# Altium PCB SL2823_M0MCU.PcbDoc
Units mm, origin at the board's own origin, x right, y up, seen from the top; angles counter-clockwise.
Board outline 146.3 x 32.54 mm, 2 copper layers (TopLayer, BottomLayer); 114 components, 64 nets, 342 pads, 170 vias.
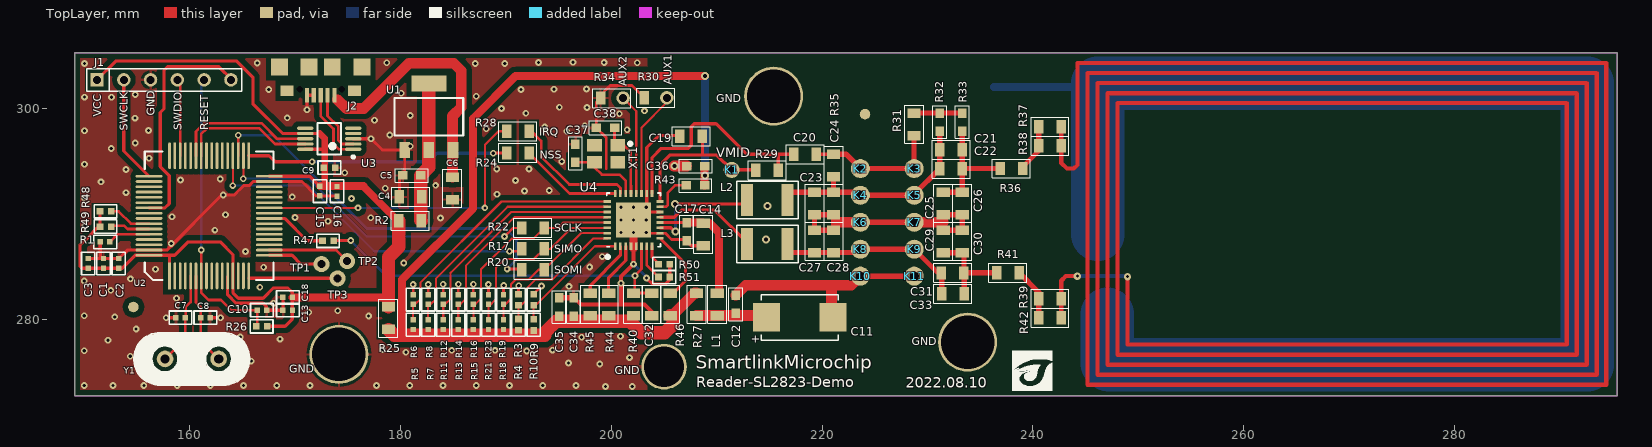
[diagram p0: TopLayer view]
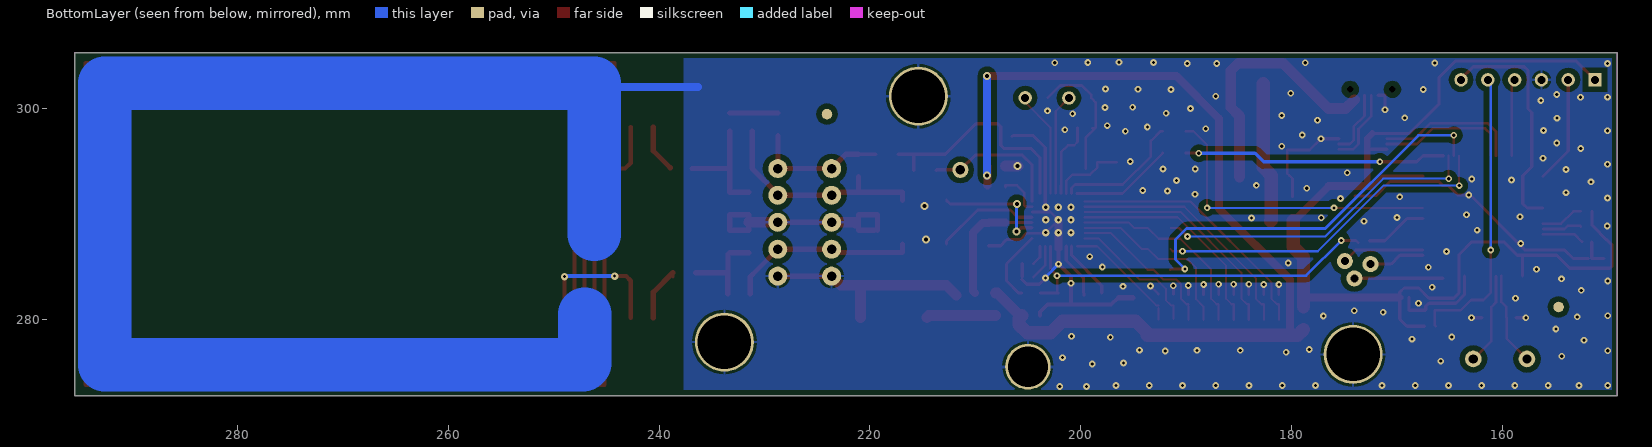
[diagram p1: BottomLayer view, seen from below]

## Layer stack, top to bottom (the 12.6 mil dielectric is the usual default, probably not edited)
TopSolder: solder mask 0.0102, Solder Resist, Dk 3.5
TopLayer: signal copper 0.0356
Dielectric1: dielectric 0.32, FR-4, Dk 4.8
BottomLayer: signal copper 0.0356
BottomSolder: solder mask 0.0102, Solder Resist, Dk 3.5

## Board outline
149.123,272.745 149.123,305.283 295.427,305.283 295.427,272.745

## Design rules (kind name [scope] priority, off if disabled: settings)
Clearance [All] p1: gap=0.152
FabricationTestPointUsage TestPointUsage [All] p1: valid=0 allowmultiple=FALSE
FabricationTestpoint Testpoint [All] p1: side=3 testpointundercomponent=TRUE minsize=1.016 maxsize=2.54 preferedsize=1.524 minholesize=0.508 maxholesize=1.016 preferedholesize=0.813 testpointgrid=0.025 allowsidetop=TRUE allowsidebottom=TRUE usegrid=TRUE gridtolerance=0
HoleSize [All] p1: absolutevalues=TRUE maxlimit=5.08 minlimit=0.025 maxpercent=80.000 minpercent=20.000
PolygonConnect [IsVia] p1: connectstyle=Direct reliefconductorwidth=0.254 reliefentries=4 polygonreliefangle="90 Angle" airgapwidth=0.254
PolygonConnect PolygonConnect_1 [All] p2: connectstyle=Relief reliefconductorwidth=0.254 reliefentries=4 polygonreliefangle="90 Angle" airgapwidth=0.254
RoutingVias [All] p1: holewidth=0.381 width=0.762 viastyle="Through Hole" minholewidth=0.254 minwidth=0.508 maxholewidth=0.508 maxwidth=1.27
SolderMaskExpansion [All] p1: expansion=0.102
Width [All] p1: maxlimit=7.62 minlimit=0.076 preferedwidth=0.203
27 further rules are at their usual default settings.

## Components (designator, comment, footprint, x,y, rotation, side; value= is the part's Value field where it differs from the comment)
C1 "100p" C_0402#1 151.867,284.836 r90 top
C2 "Cap" C_0402#1 153.314,284.836 r90 top
C3 "0.1u" C_0402#1 150.419,284.836 r90 top
C4 "10uF" Y0805#1 181,291.592 r180 top
C5 "0.1uF" Y0603 181.102,293.624 r180 top
C6 "10uF" Y0805#1 184.963,292.405 r270 top
C7 "12pF" C_0402#1 158.725,280.137 r0 top
C8 "12pF" C_0402#1 161.087,280.137 r0 top
C9 "Cap" C_0402#2 172.847,294.361 r0 top
C10 "2.2uF" C_0402#1 166.446,280.848 r0 top
C11 "330uF" C_TANTAL_D 217.881,280.162 r0 top
C12 "100nF" Y0603 211.815,281.403 r270 top
C13 "0.1uF" C_0402#1 169.799,280.848 r180 top
C14 "100pF" Y0805#1 208.737,288.036 r90 top
C15 "Cap" C_0402#1 172.39,291.694 r90 top
C16 "Cap" C_0402#1 174.015,292.583 r270 top
C17 "100nF" Y0603 207.162,288.29 r90 top
C18 "100p" C_0402#1 169.799,282.067 r180 top
C19 "1nF" Y0805#1 207.594,297.332 r180 top
C20 "1nF" Y0805#1 218.392,295.628 r0 top
C21 "12pF" Y0805#1 232.242,296.078 r0 top
C22 "27pF" Y0805#1 232.242,294.278 r0 top
C23 "270pF" Y0805#1 219.292,290.978 r90 top
C24 "NC" Y0805#1 221.092,290.978 r90 top
C25 "100pF" Y0805#1 231.492,290.978 r90 top
C26 "6pF" Y0805#1 233.292,290.978 r90 top
C27 "270pF" Y0805#1 219.292,287.378 r90 top
C28 "NC" Y0805#1 221.092,287.378 r90 top
C29 "100pF" Y0805#1 231.492,287.378 r90 top
C30 "6pF" Y0805#1 233.292,287.378 r90 top
C31 "27pF" Y0805#1 232.392,284.378 r0 top
C32 "Cap" Y0805#1 203.871,281.407 r90 top
C33 "12pF" Y0805#1 232.412,282.408 r0 top
C34 "100nF" Y0603 196.444,281.153 r270 top
C35 "100nF" Y0603 195.072,281.153 r270 top
C36 "100pF" Y0603 208.026,294.513 r0 top
C37 "12pF" Y0603 196.621,295.732 r270 top
C38 "12pF" Y0603 199.466,298.145 r0 top
J1 "Header 3X2" JETAG-2 151.257,302.692 r90 top
J2 "USB-B" microusb 172.466,300.558 r180 top
K1 "TP1" TEST_Point#1 211.43,294.157 r0 top
K2 "TP_0.9mm" TP_0.9mm#1 223.749,294.183 r0 top
K3 "TP_0.9mm" TP_0.9mm#2 228.742,294.278 r0 top
K4 "TP_0.9mm" TP_0.9mm#2 223.641,291.741 r0 top
K5 "TP_0.9mm" TP_0.9mm#2 228.741,291.741 r0 top
K6 "TP_0.9mm" TP_0.9mm#2 223.641,289.18 r0 top
K7 "TP_0.9mm" TP_0.9mm#2 228.741,289.18 r0 top
K8 "TP_0.9mm" TP_0.9mm#2 223.641,286.63 r0 top
K9 "TP_0.9mm" TP_0.9mm#2 228.741,286.63 r0 top
K10 "TP_0.9mm" TP_0.9mm#2 223.641,284.08 r0 top
K11 "TP_0.9mm" TP_0.9mm#2 228.741,284.08 r0 top
L1 "22nH" Y0805#1 210.058,281.407 r270 top
L2 "470nH / shielded (1210)" INDCC_1812 214.833,291.287 r0 top locked
L3 "470nH / shielded (1210)" INDCC_1812 214.833,287.122 r0 top locked
R1 "10K" R_0402#1 152.476,287.325 r180 top
R2 "16.9" Y0805#1 180.95,289.331 r0 top
R3 "16.9" R_0402#2 191.23,282.296 r270 top
R4 "16.9" R_0402#2 191.23,279.019 r90 top
R5 "0" R_0402#1 181.229,279.019 r90 top
R6 "0" R_0402#1 181.229,281.407 r90 top
R7 "0" R_0402#1 182.658,279.019 r90 top
R8 "0" R_0402#1 182.658,281.407 r90 top
R9 "16.9" R_0402#2 192.659,282.296 r270 top
R10 "16.9" R_0402#2 192.659,279.908 r270 top
R11 "0" R_0402#1 184.087,279.019 r90 top
R12 "0" R_0402#1 184.087,281.407 r90 top
R13 "0" R_0402#1 185.515,279.019 r90 top
R14 "0" R_0402#1 185.515,281.407 r90 top
R15 "0" R_0402#1 186.944,279.019 r90 top
R16 "0" R_0402#1 186.944,281.407 r90 top
R17 "0R" Y0805#1 192.583,286.664 r180 top
R18 "0" R_0402#1 189.802,279.019 r90 top
R19 "0" R_0402#1 189.802,281.407 r90 top
R20 "0R DNP" Y0805#1 192.608,284.683 r180 top
R21 "0" R_0402#1 188.373,279.019 r90 top
R22 "0R" Y0805#1 192.583,288.646 r0 top
R23 "" R_0402#1 188.373,281.407 r90 top
R24 "0R" Y0805#1 191.16,295.758 r0 top
R25 "16.9" Y0805#1 178.892,280.086 r90 top
R26 "4.7K" R_0402#2 166.421,279.324 r0 top
R27 "0R" Y0805#1 208.102,281.407 r90 top
R28 "0R" Y0805#1 191.16,297.815 r180 top
R29 "160R" Y0805#1 214.792,294.128 r180 top
R30 "NC" Y0805#2 204.216,300.99 r0 top
R31 "2k4" Y0805#1 228.727,298.475 r270 top
R32 "16.9" Y0603 231.165,298.679 r90 top
R33 "16.9" Y0603 233.299,298.679 r90 top
R34 "NC" Y0805#2 200.076,300.965 r0 top
R35 "DNP" Y0805#1 221.092,294.578 r270 top
R36 "0R" Y0805#3 239.014,294.284 r180 top
R37 "3R" Y0805#1 241.619,298.228 r180 top
R38 "3R" Y0805#1 241.619,296.428 r180 top
R39 "3R" Y0805#1 241.619,281.928 r180 top
R40 "10k" Y0805#1 202.123,281.407 r90 top
R41 "0R DNP" Y0805#3 238.684,284.404 r180 top
R42 "3R" Y0805#1 241.619,280.128 r180 top
R43 "16.9" Y0603 208.012,292.683 r180 top
R44 "16.9" Y0805#1 199.766,281.407 r90 top
R45 "16.9" Y0805#1 198.018,281.407 r90 top
R46 "0R DNP" Y0805#1 205.618,281.407 r90 top
R47 "NC" R_0402#2 172.72,287.426 r0 top
R48 "NC" R_0402#2 151.613,290.22 r0 top
R49 "NC" R_0402#2 151.613,288.773 r0 top
R50 "NC" R_0402#2 205.486,285.217 r180 top
R51 "0R" R_0402#2 205.486,283.997 r180 top
TP1 "Test_Point" TEST_Point#2 172.542,285.217 r90 top
TP2 "Test_Point" TEST_Point#2 174.981,285.496 r90 top
TP3 "Test_Point" TEST_Point#2 174.066,283.87 r90 top
U1 "RT9183-33GGF" RT9183-33GG 180.442,296.037 r0 top
U2 "STM32F051R8T6" QFN64-STM32 158.139,284.099 r0 top locked
U3 "CH340E" CH340E_MSOP10 173.279,297.104 r180 top
U4 "SL2x23" Z_QFN50P500X500X100-32N 200.387,286.908 r0 top locked
XT1 "27.12MHz" QUARTZ_32SMX 199.54,295.682 r180 top
Y1 "16MHz" Z-OSC 162.789,276.224 r180 top

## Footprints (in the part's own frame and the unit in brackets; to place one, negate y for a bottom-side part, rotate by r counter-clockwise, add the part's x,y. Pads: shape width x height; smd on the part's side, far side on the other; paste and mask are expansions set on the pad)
C_0402#1 [mil]
  rect 20x20 smd: 1(0,0) 2(36,0)
  silkscreen extent -25,-25 60,25
C_0402#2 [mil]
  rect 25x25 smd: 1(-3,0) 2(39,0)
  silkscreen extent -25,-25 60,25
C_TANTAL_D [mm]
  rect 2.55x2.7 smd: 1(-3.15,0) 2(3.15,0)
  silkscreen extent -3.65,-2.15 3.65,2.15
CH340E_MSOP10 [mm] "SSOP, 10-Leads, Body 3.00x3.00mm, Pitch 0.50mm, IPC Medium Density"
  oval 1.55x0.3 smd: 1(-2.275,1) 2(-2.275,0.5) 3(-2.275,0) 4(-2.275,-0.5) 5(-2.275,-1) 6(2.275,-1) 7(2.275,-0.5) 8(2.275,0) 9(2.275,0.5) 10(2.275,1)
  silkscreen extent -2.4,-1.5 1.1,1.85, body extent -1.5,-1.5 1.5,1.5, height 2.65
INDCC_1812 [mil]
  rect 45x120 smd: 1(-76,0) 2(74,0)
  silkscreen extent -114,-70 114,70
JETAG-2 [mil]
  rect 50x50 hole 30: 1(0,0)
  round 50 hole 30: 2(0,-100) 3(0,-200) 4(0,-300) 5(0,-400) 6(0,-500)
  silkscreen extent -43,-540 42,39
microusb [mm]
  rect 1.6x1.6 smd: 0(-3.901,-3.35) 0(-1.1,-3.35) 0(1.1,-3.35) 0(3.901,-3.35)
  rect 1.2x1 smd: 0(-3.2,-1.1) 0(3.2,-1.1)
  rect 0.4x1.35 smd: 1(-1.3,-0.675) 2(-0.65,-0.675) 3(0,-0.675) 4(0.65,-0.675) 5(1.3,-0.675)
  round 0 hole 0.6: ""(-2,-1.227) ""(2,-1.227)
QFN64-STM32 [mm]
  rect 0.254x2.54 smd: 1(0,0)
  oval 0.254x2.54 smd: 2(0.5,0) 3(1,0) 4(1.5,0) 5(2,0) 6(2.5,0) 7(3,0) 8(3.5,0) 9(4,0) 10(4.5,0) 11(5,0) 12(5.5,0) 13(6,0) 14(6.5,0) 15(7,0) 16(7.5,0) 33(7.5,11.4) 34(7,11.4) 35(6.5,11.4) 36(6,11.4) 37(5.5,11.4) 38(5,11.4) 39(4.5,11.4) 40(4,11.4) 41(3.5,11.4) 42(3,11.4) 43(2.5,11.4) 44(2,11.4) 45(1.5,11.4) 46(1,11.4) 47(0.5,11.4) 48(0,11.4)
  oval 2.54x0.254 smd: 17(9.45,1.95) 18(9.45,2.45) 19(9.45,2.95) 20(9.45,3.45) 21(9.45,3.95) 22(9.45,4.45) 23(9.45,4.95) 24(9.45,5.45) 25(9.45,5.95) 26(9.45,6.45) 27(9.45,6.95) 28(9.45,7.45) 29(9.45,7.95) 30(9.45,8.45) 31(9.45,8.95) 32(9.45,9.45) 49(-1.95,9.45) 50(-1.95,8.95) 51(-1.95,8.45) 52(-1.95,7.95) 53(-1.95,7.45) 54(-1.95,6.95) 55(-1.95,6.45) 56(-1.95,5.95) 57(-1.95,5.45) 58(-1.95,4.95) 59(-1.95,4.45) 60(-1.95,3.95) 61(-1.95,3.45) 62(-1.95,2.95) 63(-1.95,2.45) 64(-1.95,1.95)
  silkscreen extent -2.35,-0.4 9.85,11.8
QUARTZ_32SMX [mm]
  rect 1.4x1.2 smd: 1(-1.1,-0.8) 2(1.1,-0.8) 3(1.1,0.8) 4(-1.1,0.8)
  silkscreen extent -2.42,-1.1 -2.13,-0.8
R_0402#1 [mil]
  rect 20x20 smd: 1(0,0) 2(36,0)
  silkscreen extent -25,-25 60,25
R_0402#2 [mil]
  rect 25x25 smd: 1(-3,0) 2(39,0)
  silkscreen extent -25,-25 60,25
RT9183-33GG [mm]
  rect 1x1.5 smd: 1(0,0) 2(2.286,0) 3(4.572,0)
  rect 3.3x1.5 smd: 4(2.286,6.299)
  silkscreen extent -0.97,1.37 5.54,4.93
TEST_Point#1 [mil]
  round 60 hole 35: 1(0,0)
TEST_Point#2 [mil]
  round 60 hole 30: 1(0,0)
TP_0.9mm#1 [mm]
  round 1.8 hole 0.9: 1(-0.108,0.095)
TP_0.9mm#2 [mm]
  round 1.8 hole 0.9: 1(0,0)
Y0603 [mm]
  rect 0.9x0.8 smd: 1(-0.864,0) 2(0.864,0)
  silkscreen extent -1.55,-0.65 1.55,0.65
Y0805#1 [mm]
  rect 0.9x1.27 smd: 1(-1.067,0) 2(1.067,0)
  silkscreen extent -1.8,-0.9 1.8,0.9
Y0805#2 [mm]
  rect 0.9x1.27 smd: 1(-1.067,0)
  round 1.27 hole 0.762: 2(1.067,0)
  silkscreen extent -1.8,-0.9 1.8,0.9
Y0805#3 [mm] "Capacitor, Ceramic, R , L"
  rect 0.9x1.27 smd: 1(0,0) 2(2.134,0)
  silkscreen extent -0.73,-0.9 2.87,0.9
Z-OSC [mil]
  round 62 hole 35: 1(0,0) 2(200,0)
  silkscreen extent -116,-98 316,99
Z_QFN50P500X500X100-32N [mm] "QFN32"
  rect 0.25x0.7 smd: 1(0,0) 2(0.5,0) 3(1,0) 4(1.5,0) 5(2,0) 6(2.5,0) 7(3,0) 8(3.5,0) 17(3.5,5) 18(3,5) 19(2.5,5) 20(2,5) 21(1.5,5) 22(1,5) 23(0.5,5) 24(0,5)
  rect 0.7x0.25 smd: 9(4.25,0.75) 10(4.25,1.25) 11(4.25,1.75) 12(4.25,2.25) 13(4.25,2.75) 14(4.25,3.25) 15(4.25,3.75) 16(4.25,4.25) 25(-0.75,4.25) 26(-0.75,3.75) 27(-0.75,3.25) 28(-0.75,2.75) 29(-0.75,2.25) 30(-0.75,1.75) 31(-0.75,1.25) 32(-0.75,0.75)
  rect 3.3x3.3 smd paste-5 mask+0.102: 33(1.75,2.5)
  silkscreen extent -0.85,-1.15 4.3,5.05, body extent -0.8,-0.05 4.3,5.05, height 1

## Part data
C1 C3 C4 C5 C6 C7 C8 C10 C13 C18: library part CAP, "Capacitor"
C2 C9 C15 C16 C32: "Capacitor"
C11: library part C_TANTAL_D, "C_TANTAL_D"
C12 C17 C19 C34 C35 C36 C37 C38: library part CAPC0603, "CAPC0603"
C14 C20 C21 C22 C23 C24 C25 C26 C27 C28 C29 C30 C31 C33: library part CAPC0805, "CAPC0805"
J1: "Header, 3-Pin, Dual row"
J2: library part "Header 5", "Header, 5-Pin"
L1: library part INDC0805, "INDC0805"
L2 L3: library part INDC1812, "INDC1812"
R1 R5 R6 R7 R8 R11 R12 R13 R14 R15 R16 R18 R19 R21 R23 R26 R47 R48 R49 R50 R51: library part RES2
R2 R3 R4 R9 R10 R22 R24 R25 R28 R30 R32 R33 R34 R43 R44 R45: library part Res2, "0"
R17 R20 R27 R29 R31 R35 R36 R37 R38 R39 R40 R41 R42 R46: library part RESC0805, "RESC0805"
U3: library part CH340-E
U4: library part SL2523, "SL2523"
XT1: library part QUARTZ_32SMX, "QUARTZ_32SMX"
Y1: library part CRYSTAL, "Crystal"

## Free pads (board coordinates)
  round 1 smd: 0(154.711,281.153) 0(224.079,299.441)
  round 1 smd far side: 0(154.711,281.153) 0(224.079,299.441)
  round 5.588 hole 5.08: 0(174.193,276.657) 0(215.417,301.142) 0(233.807,277.825)
  round 4.318 hole 3.81: 0(205.029,275.488)

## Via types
v1: diameter 0.635, hole 0.305, TopLayer to BottomLayer, tented both sides, 152 vias
v2: diameter 0.7, hole 0.3, TopLayer to BottomLayer, 9 vias
v3: diameter 0.762, hole 0.381, TopLayer to BottomLayer, tented both sides, 7 vias
v4: diameter 0.7, hole 0.3, TopLayer to BottomLayer, tented both sides, 2 vias

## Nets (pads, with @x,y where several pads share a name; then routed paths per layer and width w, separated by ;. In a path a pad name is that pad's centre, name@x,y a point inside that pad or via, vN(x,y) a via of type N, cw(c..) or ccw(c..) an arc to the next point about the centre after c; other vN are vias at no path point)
D1/ADR_5: R5.2 R6.1 U4.25 | length 24.8
  TopLayer w0.203: R5.2 R6.1 181.407,281.407 181.94,281.94 181.94,283.489 189.609,291.158 U4.25
D2/ADR_4: R7.2 R8.1 U4.26 | length 23.4
  TopLayer w0.203: R7.2 R8.1 182.88,281.407 183.413,281.94 183.413,283.87 190.201,290.658 U4.26
D3/ADR_3: R11.2 R12.1 U4.27 | length 22.1
  TopLayer w0.203: R11.2 R12.1 184.252,281.407 184.785,281.94 184.785,284.404 190.539,290.158 U4.27
D4/ADR_2: R13.2 R14.1 U4.28 | length 20.8
  TopLayer w0.203: R13.2 R14.1 185.699,281.407 186.233,281.94 186.233,285.064 190.827,289.658 U4.28
DVDD: C34.2 C35.2 C36.2 R4.1 R5.1 R7.1 R10.2 R11.1 R13.1 R15.1 R18.1 R21.1 R25.1 R27.2 R40.1 R43.1 R44.1 R45.1 R46.1 | length 91.4
  TopLayer w0.762: 180.188,278.46 180.188,283.769 186.893,290.474 186.893,299.009 190.932,303.047 v3(208.89,303.047) ; C36.2 208.875,294.499 R43.1 R43.1@208.904,292.711
  TopLayer w1.016: R46.1 205.791,280.34 207.924,282.473 R27.2
  TopLayer w1.27: R25.1 179.451,278.46 180.188,278.46 188.373,278.46 193.472,278.46 ; 193.726,278.46 193.472,278.46 ; R46.1 205.867,280.091 205.867,279.476 205.105,278.714 202.87,278.714 201.778,279.806 194.818,279.806 193.472,278.46
  BottomLayer w0.762: v3(208.89,293.624) v3(208.89,303.047)
EA: R3.2 R4.2 U4.32 | length 13
  TopLayer w0.203: R4.2 R3.2 191.465,281.305 191.948,281.788 191.948,282.88 192.811,283.743 194.412,283.743 198.326,287.658 U4.32
GND: C1.2 C2.2 C3.2 C4.2 C5.2 C6.2 C7.1 C8.2 C9.2 C10.2 C11.2 C12.1 C13.2 C14.1 C15.1 C16.2 C17.1 C18.2 C19.2 C23.1 C24.1 C25.1 C26.1 C27.2 C28.2 C29.2 C30.2 C32.1 C34.1 C35.1 C36.1 C37.1 C38.1 J1.3 J2.4 J2.5 K6.1 K7.1 K10.1 K11.1 pad.0@174.193,276.657 pad.0@205.029,275.488 pad.0@215.417,301.142 pad.0@233.807,277.825 R1.2 R3.1 R6.2 R8.2 R9.1 R12.2 R14.2 R16.2 R19.2 R23.2 R30.1 R34.1 R50.1 R51.1 U1.1 U2.12 U2.31 U2.63 U3.3 U4.4 U4.5 U4.10 U4.14 U4.18 U4.33 | length 307.9
  TopLayer w0.254: U2.31 170.679,293.049 172.034,291.694 C15.1 ; C15.1@172.39,291.668 C16.2 ; v1(177.241,297.104) 178.308,296.037 U1.1 180.442,293.827 C5.2 179.934,293.319 C4.2 ; R6.2 v1(181.229,283.286) ; v1@182.651,283.286 v1(182.658,283.28) R8.2 ; R12.2 184.087,283.426 v1@184.099,283.439 ; R14.2 185.515,283.305 v1(185.522,283.312) ; R16.2 v1@186.944,283.261 ; v1@188.366,283.261 188.373,283.254 R23.2 ; R19.2 189.802,283.172 v1(189.814,283.185) ; R3.1@191.237,282.365 R3.1 191.23,283.047 v1@191.237,283.053 ; R9.1 v1@193.446,283.159 ; C38.1@198.656,298.102 C38.1@198.9,298.102 ; 199.542,294.284 199.542,297.205 C38.1 198.603,300.558 R34.1 199.009,301.244 199.923,302.158 201.981,302.158 R30.1 ; v2(202.137,289.408) 203.031,288.513 v2(203.337,288.208) 203.387,288.158 U4.10 205.135,288.158 205.74,287.553 C17.1@207.035,287.553
  TopLayer w0.3: K10.1@223.526,283.496 K10.1@223.844,283.496
  TopLayer w0.305: C3.2 151.587,285.75 151.562,285.775 R1.2 ; C1.2 C2.2 154.113,286.549 U2.63 157.873,286.549 163.093,291.77 164.262,291.77 165.151,292.659 165.684,292.659 166.074,293.049 U2.31 ; v1(157.81,280.137) C7.1 ; C8.2 v1(162.966,280.137) ; U2.12 163.639,282.309 164.44,281.508 167.005,281.508 167.31,281.203 167.31,280.899 C10.2 C13.2 C18.2 ; v1@171.171,299.847 v1(171.166,299.852) J2.5 J2.4 ; U3.3 v1(177.241,297.104) ; v2(202.137,289.408) U4.33@202.887,290.158 ; v2(203.337,290.608) U4.33@202.887,290.158 ; v1(203.352,283.896) 203.937,283.312 205.156,283.312 R51.1@205.613,283.769 ; U4.33@203.387,290.658 U4.18 203.387,296.275 204.521,297.409 206.451,297.409 C19.2 ; U4.14 U4.33@202.887,290.158 ; R51.1 R50.1@205.562,285.267 ; C17.1@207.035,287.553 C17.1 207.62,286.969 C14.1
  TopLayer w0.381: C34.1 196.494,282.016 197.129,281.381 200.939,281.381 ; 202.133,286.69 v1(202.133,285.217) 200.939,284.023 200.939,281.381 ; C32.1 203.871,280.685 203.175,281.381 200.939,281.381
  TopLayer w0.508: C35.1 C34.1 ; C27.2 C23.1 C24.1 C28.2 C27.2@219.583,288.445 ; K10.1 K11.1 ; K6.1 K7.1 ; C25.1 C25.1@231.593,289.911 ; C25.1@231.597,289.916 C25.1@231.593,289.911 ; C25.1@231.593,289.911 231.492,289.81 231.492,289.204 C29.2 C30.2 C26.1 C25.1@231.593,289.911
  TopLayer w0.762: 202.133,286.69 202.137,286.693 v2(202.137,289.408)
  TopLayer w1.016: v3@205.969,294.488 v3(205.994,294.513) C36.1 ; C12.1 212.758,283.21 220.98,283.21 ; C11.2@220.904,280.162 220.904,283.134 220.98,283.21 ; 221.412,289.103 221.489,289.18 K6.1 ; K10.1 222.771,283.21 220.98,283.21 ; K7.1 231.467,289.18 231.492,289.204
  BottomLayer w0.305: v1(202.133,285.217) 203.352,283.997 v1(203.352,283.896)
  BottomLayer w0.762: 236.296,302.031 244.246,302.031
  BottomLayer w5.08: 246.139,288.058 246.139,302.383 292.539,302.358 292.539,275.683 292.514,275.658 247.214,275.658 247.064,275.808 247.064,280.483
  other v1: 199.466,273.609 202.006,273.609 150.038,273.71 152.781,273.71 155.703,273.71 158.855,273.71 162.006,273.71 165.157,273.71 168.308,273.71 171.459,273.71 177.761,273.71 180.912,273.71 184.063,273.71 187.214,273.71 190.366,273.71 193.517,273.71 196.668,273.71 198.933,275.742 195.961,275.844 165.887,276.022 201.752,276.352 154.407,276.479 180.543,276.86 191.999,276.987 150.038,277.012 184.887,277.038 189.001,277.038 194.437,277.063 178.359,277.114 152.298,278.003 168.605,278.105 197.206,278.282 164.846,278.308 200.889,278.384 154.965,279.07 152.933,280.213 177.013,280.289 150.038,280.314 171.348,280.645 174.092,280.797 167.996,281.508 158.801,281.991 152.552,282.727 166.7,283.032 196.012,283.108 193.396,283.134 191.237,283.159 188.366,283.286 184.074,283.312 186.944,283.312 200.939,283.413 150.038,283.616 154.432,283.82 156.794,284.734 167.056,284.912 197.968,284.937 180.34,285.318 199.161,285.928 165.329,286.41 158.293,287.172 162.433,288.442 150.089,288.823 173.152,289.281 183.82,289.585 177.216,289.611 170.028,289.636 158.369,289.712 163.449,289.89 175.387,291.44 150.063,291.49 169.774,291.592 163.22,291.77 189.179,291.846 154,291.998 191.795,292.151 194.132,292.202 178.587,292.405 183.363,292.684 151.638,293.014 190.932,293.141 159.182,293.192 162.941,293.294 174.752,293.878 154,294.183 189.154,294.234 192.227,294.234 150.063,294.678 195.326,294.945 156.185,295.25 152.603,296.189 180.95,296.393 154.889,296.697 179.019,297.459 195.783,297.815 150.063,297.866 156.134,297.891 201.524,297.967 188.163,298.044 193.7,298.221 197.51,298.348 177.571,298.856 154.864,299.06 169.291,299.085 180.95,299.314 200.787,299.466 191.922,299.517 203.175,299.745 189.611,299.974 197.714,300.076 195.097,300.101 156.388,300.736 150.063,301.053 152.629,301.041 187.223,301.142 154.889,301.295 180.111,301.422 167.538,301.777 191.465,301.777 194.589,301.803 197.663,301.828 150.063,304.241 187.122,304.241 189.916,304.241 166.446,304.292 178.74,304.317 202.489,304.317 193.116,304.343 199.339,304.343 196.393,304.368
  other v2: 200.937,288.208 202.137,288.208 200.937,289.408 203.337,289.408 200.937,290.608 202.137,290.608
  other v3: 214.687,287.533 214.812,290.733
I2C: R9.2 R10.1 U4.1 | length 11.1
  TopLayer w0.203: R10.1 R9.2@192.659,281.051 ; R9.2 192.862,281.305 198.465,286.908 U4.1
I2C1_SCL: R48.2 U2.58 | length 4.1
  TopLayer w0.254: R48.2 153.289,290.22 154.46,289.049 U2.58
I2C1_SDA: R49.2 U2.59 | length 3.7
  TopLayer w0.254: R49.2 152.679,288.849 153.848,288.849 154.148,288.549 U2.59
IRQ: R28.1 U4.23 | length 12.3
  TopLayer w0.254: R28.1 192.456,297.815 193.37,296.901 193.37,295.427 196.037,292.76 200.568,292.76 200.887,292.441 U4.23
NetC4_1: C4.1 C5.1 R2.2 U1.2 U1.4 | length 13.3
  TopLayer w1.27: R2.2 181.966,289.382 C5.1 182.728,294.386 U1.2 U1.4
NetC7_2: C7.2 U2.5 Y1.2 | length 8.9
  TopLayer w0.254: Y1.2 159.639,278.154 C7.2 159.664,280.162 159.664,281.153 160.139,281.627 U2.5
NetC8_1: C8.1 U2.6 Y1.1 | length 8.8
  TopLayer w0.254: U2.6 160.639,281.6 161.087,281.153 C8.1 161.087,277.926 Y1.1
NetC11_1: C11.1 C12.2 L1.2 R27.1 | length 6.6
  TopLayer w1.016: R27.1 L1.2 214.426,280.34 C11.1@214.604,280.162
NetC14_2: C14.2 C17.2 L1.1 U4.12 | length 11.9
  TopLayer w0.305: U4.12 206.955,289.158 C17.2@207.192,289.395
  TopLayer w0.762: C17.2 208.686,289.154 C14.2 209.347,289.103 210.236,288.214 210.236,282.651 L1.1
NetC20_1: C20.1 R29.1 U4.17 | length 22.1
  TopLayer w0.305: U4.17 203.887,295.327 204.749,296.189 207.315,296.189 207.594,296.469 207.594,298.247 207.874,298.526 209.956,298.526 212.855,295.628 215.722,295.628 ; R29.1 215.859,295.492 215.722,295.628 ; C20.1@217.255,295.558 C20.1 215.722,295.628
NetC20_2: C20.2 K2.1 K3.1 R31.2 R35.1 | length 13
  TopLayer w0.3: R35.1@221.075,295.628 R35.1
  TopLayer w0.305: C20.2 R35.1@221.075,295.628
  TopLayer w0.508: R35.1 222.274,295.645 K2.1 K3.1 228.727,294.293 R31.2
NetC21_1: C21.1 C22.1 C23.2 C24.2 K4.1 K5.1 L2.2 R32.1 R35.2 | length 21.3
  TopLayer w0.508: L2.2@216.916,291.287 216.916,292.045 C23.2 C24.2 ; R35.2 C24.2 ; R32.1 231.165,296.088 C21.1 C22.1 228.741,291.844 K5.1 K4.1 223.337,292.045 C24.2
NetC21_2: C21.2 C22.2 C25.2 C26.2 R33.1 R36.2 | length 11.2
  TopLayer w0.508: C25.2 C26.2 233.309,292.062 C22.2 ; R33.1 233.299,296.088 C21.2 C22.2 ; R36.2 236.874,294.278 C22.2
NetC27_1: C27.1 C28.1 C31.1 C33.1 K8.1 K9.1 L3.2 | length 18.1
  TopLayer w0.5: L3.2@216.916,287.122 216.916,286.311 C27.1 C28.1 223.322,286.311 K8.1 K9.1 231.159,284.212 231.345,284.026 C33.1
NetC29_1: C29.1 C30.1 C31.2 C33.2 R41.2 | length 8.9
  TopLayer w0.508: C29.1 C30.1 233.459,286.144 C31.2 ; C33.2 233.479,284.358 C31.2 ; R41.2 233.484,284.404 C31.2
NetC37_2: C37.2 U4.22 XT1.3 | length 7
  TopLayer w0.254: C37.2 198.426,294.869 XT1.3 198.44,294.397 199.136,293.7 200.812,293.7 201.387,293.126 U4.22
NetC38_2: C38.2 U4.21 XT1.1 | length 7.2
  TopLayer w0.203: XT1.1@200.33,296.792 XT1.1
  TopLayer w0.254: XT1.1@200.33,296.792 C38.2 ; XT1.1 201.231,296.482 201.879,295.834 201.879,292.641 201.887,292.633 U4.21
NetL2_1: L2.1 U4.11 | length 11
  TopLayer w0.305: U4.11 205.677,288.658 v3@206.045,288.29 ; v3(206.07,290.906) 212.369,290.906 L2.1@212.75,291.287
  BottomLayer w0.305: v3(206.07,290.906) 206.096,290.881 v3(206.096,288.29)
NetL3_1: L3.1 U4.13 | length 9.9
  TopLayer w0.305: U4.13 205.99,289.658 206.68,290.347 209.779,290.347 212.75,287.376 L3.1@212.75,287.122
NetR1_1: R1.1 U2.60 | length 4
  TopLayer w0.254: R1.1 153.2,288.049 U2.60
NetR17_2: R17.2 U2.36 | length 32.9
  TopLayer w0.203: v1(164.135,292.659) 164.139,292.663 U2.36 ; v1@190.322,286.436 v1(190.373,286.436) 191.287,286.436 R17.2
  BottomLayer w0.203: v1(164.135,292.659) 171.323,292.659 177.546,286.436 v1(190.373,286.436)
NetR20_2: R20.2 U2.35 | length 37
  TopLayer w0.254: U2.35 164.639,297.43 v1(164.643,297.434) ; v1(190.144,284.759) 191.465,284.759 R20.2
  BottomLayer w0.254: v1(164.643,297.434) 167.996,297.434 176.835,288.595 189.973,288.595 191.033,287.534 191.033,285.648 v1(190.144,284.759)
NetR22_1: R22.1 U2.34 | length 31.2
  TopLayer w0.203: v1@165.125,293.268 165.139,293.282 U2.34 ; v1(189.89,287.833) 190.703,288.646 R22.1
  BottomLayer w0.203: v1(165.125,293.319) 171.348,293.319 176.835,287.833 v1@189.865,287.833
NetR24_1: R24.1 U2.33 | length 25.1
  TopLayer w0.305: U2.33 167.568,295.499 168.148,294.919 v1(171.653,294.919) ; v1@188.798,295.808 188.849,295.758 R24.1
  BottomLayer w0.305: v1(171.653,294.919) 182.677,294.919 183.49,295.732 v1(188.824,295.732)
NetR28_2: R28.2 U2.26 | length 29
  TopLayer w0.203: U2.26 175.995,290.549 v1(175.997,290.551) ; v1(188.036,290.551) 188.036,296.52 189.332,297.815 R28.2
  BottomLayer w0.203: v1(175.997,290.551) v1(188.036,290.551)
NetR30_2: R30.2 U4.19 | length 10.1
  TopLayer w0.203: U4.19 202.887,298.162 205.283,300.558 R30.2
NetR31_1: R31.1 R32.2 R33.2 | length 4.6
  TopLayer w0.508: R31.1 R32.2 R33.2
NetR34_2: R34.2 U4.20 | length 9.6
  TopLayer w0.203: R34.2 202.387,299.72 U4.20
NetR36_1: R36.1 R37.2 R38.2 | length 4.7
  TopLayer w0.3: R36.1@238.942,294.352 R36.1@238.942,294.46
  TopLayer w0.5: R36.1@238.942,294.352 240.553,295.963 R38.2 R37.2
NetR37_1: R37.1 R38.1 R39.1 R42.1 | length 731
  TopLayer w0.4: R42.1 R39.1 242.686,283.645 243.119,284.078 v4(244.219,284.078) ; R37.1 242.686,295.983 242.686,294.811 243.219,294.278 243.869,294.278 244.219,294.628 244.219,304.278 294.369,304.278 294.369,273.778 245.169,273.778 245.169,303.328 293.469,303.328 293.469,274.728 246.119,274.728 246.119,302.378 292.519,302.378 292.519,275.678 247.069,275.678 247.069,301.428 291.569,301.428 291.569,276.628 248.019,276.628 248.019,284.078 248.019,300.478 ; 248.019,300.453 248.024,300.458 ; 248.024,300.483 290.614,300.483 290.614,277.583 248.964,277.583 v4(248.964,284.033)
  BottomLayer w0.4: v4@244.138,284.083 v4@249.039,284.083
NetR39_2: R39.2 R41.1 R42.2 | length 5.4
  TopLayer w0.305: R41.1@238.689,284.008 R41.1@238.689,284.358
  TopLayer w0.508: R41.1 240.553,282.535 R39.2 R42.2
NetR43_2: R43.2 U4.15 | length 4.2
  TopLayer w0.254: U4.15 205.212,290.658 205.384,290.83 205.384,291.998 206.069,292.683 R43.2
  TopLayer w0.305: R43.2@207.148,292.543 R43.2
NetR44_2: R44.2 U4.3 | length 5.3
  TopLayer w0.305: R44.2@199.698,282.27 R44.2@199.698,282.473 ; R44.2 199.766,283.942 201.387,285.562 U4.3
NetR45_2: R45.2 U4.2 | length 5.6
  TopLayer w0.305: R45.2 198.018,283.185 200.887,286.053 U4.2
NetR46_2: R46.2 U4.9 | length 6.9
  TopLayer w0.305: U4.9 207.061,285.234 207.061,283.642 205.892,282.473 R46.2
NetR47_1: R47.1 U2.24 | length 5.9
  TopLayer w0.305: U2.24 169.048,289.549 171.171,287.426 R47.1
NetR50_2: R50.2 U4.8 | length 1.9
  TopLayer w0.254: U4.8 203.887,285.876 R50.2@204.495,285.267
NetR51_2: R51.2 U4.7 | length 3.4
  TopLayer w0.254: U4.7 203.387,285.106 R51.2
NetTP1_1: TP1.1 U2.17 | length 5.4
  TopLayer w0.305: U2.17 169.754,286.049 170.586,285.217 TP1.1 ; TP1.1@172.441,285.521 172.466,285.496 TP1.1@172.491,285.496
NetTP2_1: TP2.1 U2.18 | length 8.2
  TopLayer w0.254: U2.18 173.928,286.549 175.057,285.42 TP2.1@175.057,285.115
NetTP3_1: TP3.1 U2.16 | length 8.4
  TopLayer w0.305: U2.16@165.673,283.87 TP3.1
NRSTPD: C32.2 R40.2 R47.2 U4.6 | length 36.5
  TopLayer w0.254: R47.2@173.711,287.249 173.914,287.452 v1(175.311,287.452) ; R40.2 R40.2@202.159,282.509 ; R40.2@202.26,282.509 v1(202.26,284.124) 202.887,284.751 U4.6
  TopLayer w0.305: R40.2 C32.2
  BottomLayer w0.254: v1(175.311,287.452) 178.638,284.124 v1(202.26,284.124)
NSS: R24.2 U4.24 | length 9.8
  TopLayer w0.254: R24.2 196.077,291.908 U4.24
RESET/: C10.1 J1.5 R26.1 U2.7 | length 27.9
  TopLayer w0.254: v1(161.138,286.563) 161.139,286.561 U2.7 161.139,282.523 161.849,281.813 163.017,281.813 163.982,280.848 C10.1 166.446,279.425 R26.1
  BottomLayer w0.254: v1(161.138,286.563) 161.138,302.311 J1.5@161.519,302.692
RX_UART: U2.43 U3.8 | length 13.6
  TopLayer w0.254: U2.43 160.639,297.774 161.442,298.577 166.853,298.577 168.326,297.104 U3.8
SCLK: R15.2 R16.1 R22.2 U4.29 | length 19
  TopLayer w0.203: R15.2 R16.1 187.122,281.407 187.655,281.94 187.655,284.709 190.576,287.63 192.634,287.63 R22.2 194.945,288.646 195.457,289.158 U4.29
SIMO: R17.1 R21.2 R23.1 U4.30 | length 17.4
  TopLayer w0.203: R21.2 188.373,281.184 189.078,281.889 189.078,284.861 189.916,285.699 192.684,285.699 R17.1 194.259,286.664 196.253,288.658 U4.30
SOMI: R18.2 R19.1 R20.1 U4.31 | length 14.7
  TopLayer w0.203: R18.2 R19.1@189.802,281.184 ; R19.1 189.992,281.407 190.5,281.915 190.5,283.286 190.97,283.756 192.189,283.756 193.116,284.683 R20.1 197.15,288.158 U4.31
SWCLK_1: J1.2 U2.49 | length 10.1
  TopLayer w0.305: J1.2 153.797,295.941 U2.49
SWDIO_1: J1.4 U2.46 | length 7.3
  TopLayer w0.254: J1.4@158.979,302.692 159.139,302.531 U2.46
SWO: J1.6 U2.55 | length 22.3
  TopLayer w0.305: U2.55 157.707,290.549 158.115,290.957 158.115,293.599 157.251,294.462 157.251,299.593 157.607,299.949 157.607,303.581 157.963,303.936 162.814,303.936 J1.6@164.059,302.692
TX_UART: U2.42 U3.9 | length 12.8
  TopLayer w0.254: U2.42 161.139,297.563 161.671,298.094 166.649,298.094 168.14,296.604 U3.9
USBD+: J2.3 U3.1 | length 7.2
  TopLayer w0.254: J2.3 172.466,299.263 173.685,298.044 173.685,296.621 174.203,296.104 U3.1
USBD-: J2.2 U3.2 | length 6.3
  TopLayer w0.254: J2.2 173.116,299.273 174.142,298.247 174.142,296.959 174.498,296.604 U3.2
VCC: C1.1 C2.1 C3.1 C9.1 C13.1 C15.2 C16.1 C18.1 J1.1 R2.1 R25.2 R26.2 R48.1 R49.1 U2.1 U2.13 U2.32 U2.64 U3.7 U3.10 | length 104.2
  TopLayer w0.305: J1.1 153.035,304.47 164.516,304.47 166.04,302.946 166.04,300.431 168.867,297.604 U3.7 172.372,297.604 ; R48.1 151.536,288.9 150.127,287.49 150.085,287.49 149.657,287.062 149.657,285.013 149.835,284.836 C3.1 C1.1 C2.1 153.67,284.836 154.883,286.049 U2.64 158.242,286.049 ; U2.1 158.139,285.946 158.242,286.049 ; R26.2 169.088,279.324 169.774,280.01 169.774,282.55 169.367,282.956 167.97,282.956 167.005,281.991 164.668,281.991 164.139,282.52 U2.13 164.139,286.127 162.941,287.325 159.893,287.325 158.617,286.049 158.242,286.049 ; U2.32 171.423,293.549 C15.2@172.39,292.583 ; U3.10 172.729,296.104 ; C16.1@173.965,292.583 C16.1
  TopLayer w0.635: 172.372,297.604 172.847,297.129 172.847,292.608
  TopLayer w0.762: C18.1 178.816,282.067 178.892,281.991 ; C15.2 172.847,292.608 176.505,292.608 179.781,289.331 R2.1
  TopLayer w1.27: R25.2 178.892,281.991 178.892,285.852 179.883,286.842 R2.1
VCC_5V: C6.1 J2.1 U1.3 | length 24.6
  TopLayer w1.016: 174.066,300.812 174.904,299.974 176.555,299.974 180.848,304.267 185.09,304.267 185.801,303.555 185.801,300.101 184.963,299.263 C6.1
VMID: C19.1 K1.1 R29.2 U4.16 | length 15.3
  TopLayer w0.305: U4.16 204.637,294.64 205.551,295.554 208.686,295.554 ; C19.1 208.661,295.58 208.686,295.554 ; R29.2 213.696,294.157 K1.1 210.033,295.554 208.686,295.554
pads on no net: J2. J2.0 U2.2 U2.3 U2.4 U2.8 U2.9 U2.10 U2.11 U2.14 U2.15 U2.19 U2.20 U2.21 U2.22 U2.23 U2.25 U2.27 U2.28 U2.29 U2.30 U2.37 U2.38 U2.39 U2.40 U2.41 U2.44 U2.45 U2.47 U2.48 U2.50 U2.51 U2.52 U2.53 U2.54 U2.56 U2.57 U2.61 U2.62 U3.4 U3.5 U3.6 XT1.2 XT1.4

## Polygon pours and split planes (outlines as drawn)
GND on KeepOutLayer (hatched 90Degree grid 0.254 track 0.127, remove dead copper): 172.06,309.677
GND on TopLayer "Bottom Layer-No Net" (solid, remove dead copper, pour order 30): 149.123,272.745 149.123,305.283 203.454,305.283 203.429,305.283 203.429,303.784 203.429,272.745 203.327,272.745 149.123,272.745
GND on BottomLayer "Bottom Layer-No Net" (solid, remove dead copper, pour order 32): 149.123,272.745 149.123,305.283 237.49,305.283 237.642,305.283 237.642,291.567 237.642,272.745 237.388,272.745 149.123,272.745

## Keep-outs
KeepOutLayer:
  lines w0.076: 149.123,272.745 149.123,301.6 149.123,305.283 149.555,305.283 172.314,305.283 295.173,305.283 295.427,305.283 295.427,272.745 295.197,272.745 171.358,272.745 149.123,272.745

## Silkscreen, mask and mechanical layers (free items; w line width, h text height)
TopOverlay:
  drawing of 317 lines, arcs and shapes, not listed
  text "AUX1" at 205.74,302.209 h0.76 r90
  text "AUX2" at 201.473,302.082 h0.76 r90
  text "GND" at 209.982,300.558 h0.76
  text "GND" at 156.743,299.263 h0.76 r90
  text "VCC" at 151.663,299.212 h0.76 r90
  text "SWDIO" at 159.283,297.917 h0.76 r90
  text "RESET" at 161.823,297.891 h0.76 r90
  text "SWCLK" at 154.178,297.84 h0.76 r90
  text "IRQ" at 193.192,297.383 h0.76
  text "VMID" at 209.962,295.333 h0.9
  text "NSS" at 193.218,295.224 h0.76
  text "SCLK" at 194.589,288.29 h0.76
  text "SIMO" at 194.589,286.309 h0.76
  text "SOMI" at 194.589,284.328 h0.76
  text "GND" at 228.498,277.52 h0.76
  text "SmartlinkMicrochip" at 208.051,275.285 h1.27
  text "GND" at 169.469,274.904 h0.76
  text "GND" at 200.33,274.752 h0.76
  text "Reader-SL2823-Demo" at 208.077,273.533 h1.02
  text "2022.08.10" at 227.94,273.482 h1.02

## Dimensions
149.123,305.283 to 295.427,305.283 on TopLayer
149.123,305.283 to 149.123,272.745 on TopLayer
